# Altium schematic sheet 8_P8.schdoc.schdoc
size 309 x 223 mm; Symbol: A4_Schematic_0605; Device: A4_Schematic_0605; @Project Name: MDIO-Board_Rev_01(0124); @Page Count: 10; @Update Date: 2024-05-24; @Create Date: 2024-05-19; @Schematic Name: Schematic1; @Page No: 8; @Page Name: P8
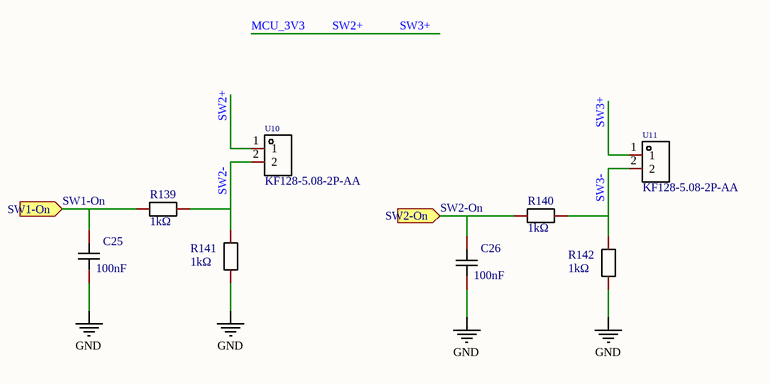
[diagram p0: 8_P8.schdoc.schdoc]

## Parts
C25  100nF  [C0603]
C26  100nF  [C0603]
R139  1kΩ  [R0603]
R140  1kΩ  [R0603]
R141  1kΩ  [R0603]
R142  1kΩ  [R0603]
U10  KF128-5.08-2P-AA  [CONN-TH_P5.08_KF128-5.08-2P]
U11  KF128-5.08-2P-AA  [CONN-TH_P5.08_KF128-5.08-2P]

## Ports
SW1-On (in), SW2-On (in)

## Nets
GND: C25.2 C26.2 R141.1 R142.1
MCU_3V3: U10.1 U11.1  [also labelled SW2+, SW3+]
SW1-On: C25.1 R139.1 ; port SW1-On
SW2-: R139.2 R141.2 U10.2
SW2-On: C26.1 R140.1 ; port SW2-On
SW3-: R140.2 R142.2 U11.2

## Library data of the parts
C25 C26 = CC0603KRX7R9BB104: Manufacturer: YAGEO(国巨); Add into BOM: yes; Tolerance: ±10%; Description: Capacitance: Tolerance:±10% Tolerance:±10% Voltage Rated: Temperature Coefficient:
R139-R142 = SCR0603J10K: Manufacturer: VO(翔胜); Add into BOM: yes; Tolerance: ±5%; Description: Type:Thick Film Resistors Resistance: Tolerance:±5% Tolerance:±5% Power(Watts): Overload Voltage (Max): Operating Temperature Range:-55℃~+155℃ Operating Temperature Range:-55℃~+155℃
U10 U11 = KF128-5.08-2P-AA: Manufacturer: KEFA(科发); Add into BOM: yes; Structure: 1x2P; Pitch: 5.08mm; Current Rating (Max): 24A; Voltage Rating (Max): 250V; Wire Gauge - AWG: 12~22; Wire Gauge - mm2: 2.5; Number of PINs Per Row: 2; Description: Structure:1x2P Pitch:5.08mm Color:Green Mounting Style:Straight Current Rating (Max):24A Voltage Rating (Max):250V Number of Pins:2P Number of Rows:1 Wire Gauge - AWG:12~22 Wire Gauge - AWG:12~22 Wire Gauge - mm2:2.5 Wire Gauge - mm2:2.5 Number of PINs Pe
